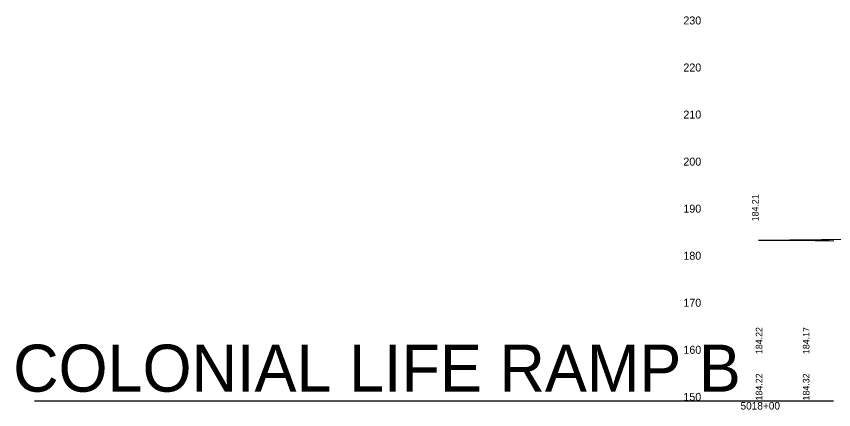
# Model space of a CAD drawing. Extents: x 1876258 to 1932803, y 754739 to 837911.
# Drawn here: x 1913676 to 1914544, y 787980 to 788398 of the extents above; entities that cross this region are included whole.
import ezdxf

# ---------------------------------------------------------------- set-up
doc = ezdxf.new("R2010")
doc.units = 0
for name, color, linetype in [('RD_DDB_ElevTX', 7, 'Continuous'), ('RD_DDB_Profile_EX', 7, 'Continuous'), ('RD_DDB_Profile_Lbl', 7, 'Continuous'), ('RD_DDB_Profile_PR', 7, 'Continuous'), ('RD_DDB_StaTX', 7, 'Continuous'), ('RD_DDB_StripGrade', 7, 'Continuous'), ('RD_Sketch8', 7, 'Continuous')]:
    doc.layers.add(name, color=color, linetype=linetype)

msp = doc.modelspace()

# ---------------------------------------------------------------- linework, layer by layer
at = {"layer": 'RD_DDB_Profile_EX'}
msp.add_lwpolyline([(1914464.26, 788160.27), (1914469.26, 788160.26), (1914474.26, 788160.24), (1914479.26, 788160.22), (1914484.26, 788160.2), (1914489.26, 788160.18), (1914494.26, 788160.17), (1914499.26, 788160.15), (1914504.26, 788160.13), (1914509.26, 788160.11), (1914514.26, 788160.06), (1914519.26, 788160.01), (1914524.26, 788159.89), (1914529.26, 788159.8), (1914534.26, 788159.72), (1914539.26, 788159.64), (1914544.26, 788159.59)], dxfattribs=at)
msp.add_lwpolyline([(1914464.26, 788160.27), (1914469.26, 788160.26), (1914474.26, 788160.24), (1914479.26, 788160.22), (1914484.26, 788160.2), (1914489.26, 788160.18), (1914494.26, 788160.17), (1914499.26, 788160.15), (1914504.26, 788160.13), (1914509.26, 788160.11), (1914514.26, 788160.06), (1914519.26, 788160.01), (1914524.26, 788159.89), (1914529.26, 788159.8), (1914534.26, 788159.72), (1914539.26, 788159.64), (1914544.26, 788159.59)], dxfattribs=at)
at = {"layer": 'RD_DDB_Profile_PR'}
msp.add_line((1914464.26, 788160.19), (1914647.14, 788161.94), dxfattribs=at)
at = {"layer": 'RD_Sketch8'}
msp.add_line((1914544, 787989.14), (1913695.26, 787989.14), dxfattribs=at)

# ---------------------------------------------------------------- texts
at = {"layer": 'RD_DDB_ElevTX'}
for s, p in [('230', (1914384.4, 788389.39)), ('220', (1914384.4, 788339.39)), ('210', (1914384.4, 788289.39)), ('200', (1914384.4, 788239.39)), ('190', (1914384.4, 788189.39)), ('180', (1914384.4, 788139.39)), ('170', (1914384.4, 788089.39)), ('160', (1914384.4, 788039.39)), ('150', (1914384.4, 787989.39))]:
    msp.add_text(s, height=8.5, dxfattribs=at).set_placement(p)
at = {"layer": 'RD_DDB_Profile_Lbl'}
msp.add_text('184.21', height=7, rotation=90, dxfattribs=at).set_placement((1914464.26, 788180.19))
at = {"layer": 'RD_DDB_StaTX'}
msp.add_text('5018+00', height=8, dxfattribs=at).set_placement((1914445.08, 787980.14))
at = {"layer": 'RD_DDB_StripGrade'}
for s, p in [('184.22', (1914468.29, 788039.14)), ('184.17', (1914518.29, 788039.14)), ('184.22', (1914468.29, 787989.89)), ('184.32', (1914518.29, 787989.89))]:
    msp.add_text(s, height=7, rotation=90, dxfattribs=at).set_placement(p)
at = {"layer": 'RD_Sketch8'}
msp.add_text('COLONIAL LIFE RAMP B', height=50, dxfattribs=at).set_placement((1913672.57, 787999.14))

doc.saveas('drawing.dxf')
